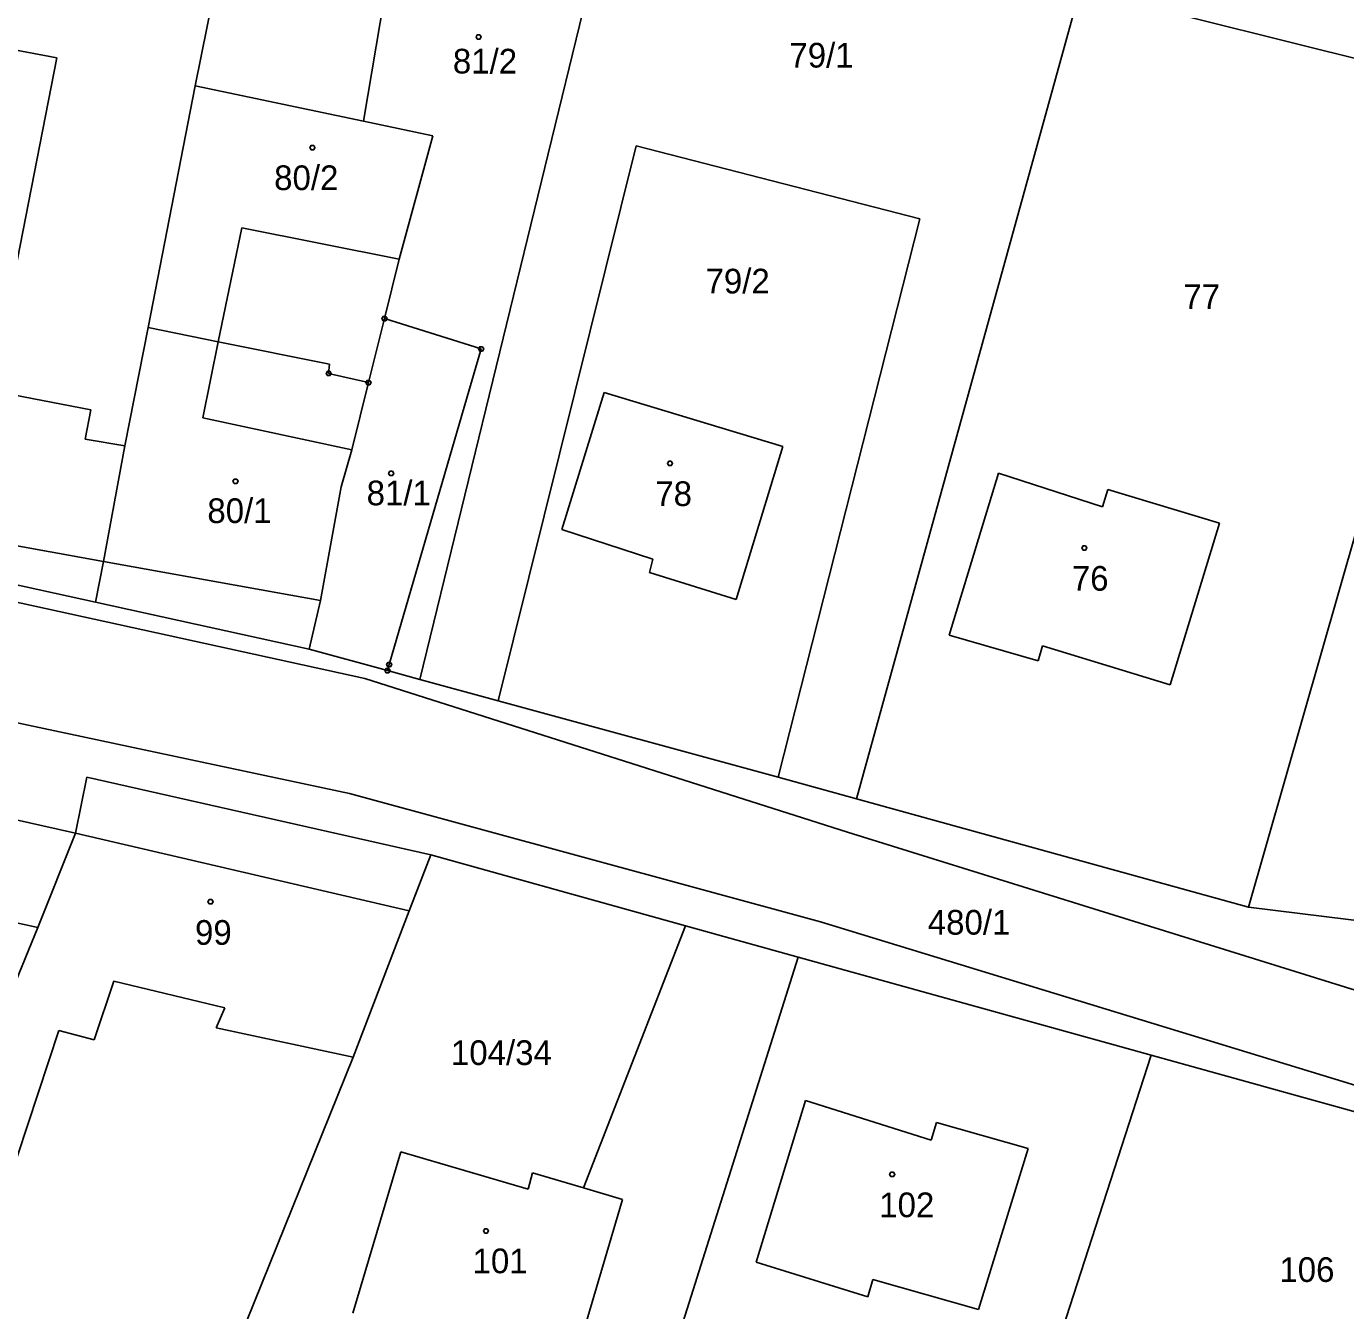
# Model space of a CAD drawing. Extents: x -634640 to -629202, y -1196156 to -1190068.
# Drawn here: x -631368.4 to -631277.6, y -1192711.2 to -1192622.8 of the extents above; entities that cross this region are included whole.
import ezdxf

# ---------------------------------------------------------------- set-up
doc = ezdxf.new("R2010")
doc.units = 0
for name, color, linetype in [('Vrstva 1', 7, 'Continuous'), ('Vrstva 2', 7, 'Continuous'), ('Vrstva 3', 7, 'Continuous'), ('Vrstva 4', 7, 'Continuous'), ('Vrstva 5', 7, 'Continuous'), ('Vrstva 8', 7, 'Continuous')]:
    doc.layers.add(name, color=color, linetype=linetype)

msp = doc.modelspace()

# ---------------------------------------------------------------- linework, layer by layer
at = {"layer": 'Vrstva 1'}
for p, q in [((-631342.04, -1192610.57), (-631345.22, -1192629.29)), ((-631341.34, -1192667.74), (-631327.93, -1192612.83)), ((-631356.81, -1192626.85), (-631354.23, -1192614.01)), ((-631311.26, -1192675.96), (-631295.87, -1192620.24)), ((-631295.87, -1192620.24), (-631268.16, -1192627.17)), ((-631360.06, -1192643.5), (-631356.81, -1192626.85)), ((-631284.27, -1192683.42), (-631268.16, -1192627.17)), ((-631345.22, -1192629.29), (-631340.44, -1192630.3)), ((-631340.44, -1192630.3), (-631342.77, -1192638.79)), ((-631335.95, -1192669.21), (-631326.44, -1192631)), ((-631326.44, -1192631), (-631306.91, -1192636.03)), ((-631306.91, -1192636.03), (-631316.66, -1192674.48)), ((-631342.77, -1192638.79), (-631343.78, -1192642.89)), ((-631343.78, -1192642.89), (-631344.88, -1192647.3)), ((-631337.12, -1192644.98), (-631343.78, -1192642.89)), ((-631361.66, -1192651.66), (-631360.06, -1192643.5)), ((-631360.06, -1192643.5), (-631355.22, -1192644.48)), ((-631355.22, -1192644.48), (-631347.55, -1192646.04)), ((-631343.45, -1192666.72), (-631337.12, -1192644.98)), ((-631347.55, -1192646.04), (-631347.62, -1192646.67)), ((-631347.62, -1192646.67), (-631344.88, -1192647.3)), ((-631344.88, -1192647.3), (-631346.02, -1192651.93)), ((-631331.57, -1192657.42), (-631328.65, -1192647.99)), ((-631328.65, -1192647.99), (-631316.34, -1192651.69)), ((-631363.12, -1192659.62), (-631361.66, -1192651.66)), ((-631346.02, -1192651.93), (-631346.75, -1192654.47)), ((-631316.34, -1192651.69), (-631319.55, -1192662.23)), ((-631304.89, -1192664.69), (-631301.49, -1192653.54)), ((-631301.49, -1192653.54), (-631294.33, -1192655.86)), ((-631346.75, -1192654.47), (-631348.17, -1192662.31)), ((-631294.33, -1192655.86), (-631293.95, -1192654.67)), ((-631293.95, -1192654.67), (-631286.25, -1192656.99)), ((-631325.28, -1192659.46), (-631331.57, -1192657.42)), ((-631286.25, -1192656.99), (-631289.67, -1192668.11)), ((-631345.12, -1192667.68), (-631387.55, -1192658.39)), ((-631363.68, -1192662.42), (-631378.54, -1192659.16)), ((-631363.68, -1192662.42), (-631363.12, -1192659.62)), ((-631325.52, -1192660.37), (-631325.28, -1192659.46)), ((-631319.55, -1192662.23), (-631325.52, -1192660.37)), ((-631348.97, -1192665.66), (-631363.68, -1192662.42)), ((-631348.17, -1192662.31), (-631348.97, -1192665.66)), ((-631298.76, -1192666.47), (-631304.89, -1192664.69)), ((-631343.57, -1192667.13), (-631348.97, -1192665.66)), ((-631298.45, -1192665.44), (-631298.76, -1192666.47)), ((-631289.67, -1192668.11), (-631298.45, -1192665.44)), ((-631384.86, -1192667.38), (-631346.18, -1192675.61)), ((-631343.57, -1192667.13), (-631343.45, -1192666.72)), ((-631341.34, -1192667.74), (-631343.57, -1192667.13)), ((-631311.89, -1192678.27), (-631345.12, -1192667.68)), ((-631335.95, -1192669.21), (-631341.34, -1192667.74)), ((-631316.66, -1192674.48), (-631335.95, -1192669.21)), ((-631365.05, -1192678.33), (-631383.23, -1192674.24)), ((-631364.28, -1192674.48), (-631365.05, -1192678.33)), ((-631340.58, -1192679.83), (-631364.28, -1192674.48)), ((-631311.26, -1192675.96), (-631316.66, -1192674.48)), ((-631346.18, -1192675.61), (-631313.75, -1192684.44)), ((-631284.27, -1192683.42), (-631311.26, -1192675.96)), ((-631365.05, -1192678.33), (-631367.66, -1192684.83)), ((-631259.47, -1192694.58), (-631311.89, -1192678.27)), ((-631340.58, -1192679.83), (-631342.08, -1192683.67)), ((-631323.05, -1192684.71), (-631340.58, -1192679.83)), ((-631342.08, -1192683.67), (-631345.92, -1192693.76)), ((-631274.56, -1192684.62), (-631284.27, -1192683.42)), ((-631367.66, -1192684.83), (-631376.35, -1192706.11)), ((-631330.07, -1192702.77), (-631323.05, -1192684.71)), ((-631315.29, -1192686.87), (-631323.05, -1192684.71)), ((-631313.75, -1192684.44), (-631261.8, -1192700.32)), ((-631315.29, -1192686.87), (-631326.27, -1192721.7)), ((-631290.96, -1192693.63), (-631315.29, -1192686.87)), ((-631345.92, -1192693.76), (-631356.56, -1192720.09)), ((-631290.96, -1192693.63), (-631302.52, -1192729.24)), ((-631262.31, -1192701.6), (-631290.96, -1192693.63)), ((-631318.17, -1192707.87), (-631314.77, -1192696.75)), ((-631314.77, -1192696.75), (-631306.11, -1192699.47)), ((-631306.11, -1192699.47), (-631305.75, -1192698.26)), ((-631305.75, -1192698.26), (-631299.44, -1192700.04)), ((-631299.44, -1192700.04), (-631302.87, -1192711.14)), ((-631345.96, -1192711.38), (-631342.65, -1192700.29)), ((-631342.65, -1192700.29), (-631333.88, -1192702.86)), ((-631333.88, -1192702.86), (-631333.57, -1192701.72)), ((-631333.57, -1192701.72), (-631330.07, -1192702.77)), ((-631330.07, -1192702.77), (-631327.38, -1192703.57)), ((-631327.38, -1192703.57), (-631330.63, -1192714.56)), ((-631310.48, -1192710.27), (-631318.17, -1192707.87)), ((-631310.14, -1192709.07), (-631310.48, -1192710.27)), ((-631302.87, -1192711.14), (-631310.14, -1192709.07))]:
    msp.add_line(p, q, dxfattribs=at)
at = {"layer": 'Vrstva 3'}
for points in [[(-631337.2, -1192623.34), (-631337.11, -1192623.49), (-631337.2, -1192623.64), (-631337.38, -1192623.64), (-631337.47, -1192623.49), (-631337.38, -1192623.34), (-631337.2, -1192623.34)], [(-631343.22, -1192653.4), (-631343.13, -1192653.55), (-631343.22, -1192653.7), (-631343.4, -1192653.7), (-631343.49, -1192653.55), (-631343.4, -1192653.4), (-631343.22, -1192653.4)]]:
    msp.add_lwpolyline(points, dxfattribs=at)
at = {"layer": 'Vrstva 4'}
for p, q in [((-631366.33, -1192624.94), (-631371.82, -1192623.91)), ((-631366.33, -1192624.94), (-631370.44, -1192645.84)), ((-631356.81, -1192626.85), (-631345.22, -1192629.29)), ((-631353.61, -1192636.65), (-631355.22, -1192644.48)), ((-631342.77, -1192638.79), (-631353.61, -1192636.65)), ((-631355.22, -1192644.48), (-631356.29, -1192649.73)), ((-631369.34, -1192648.15), (-631364, -1192649.18)), ((-631364, -1192649.18), (-631364.39, -1192651.2)), ((-631356.29, -1192649.73), (-631346.02, -1192651.93)), ((-631364.39, -1192651.2), (-631361.66, -1192651.66)), ((-631363.12, -1192659.62), (-631378.09, -1192656.92)), ((-631348.17, -1192662.31), (-631363.12, -1192659.62)), ((-631365.05, -1192678.33), (-631342.08, -1192683.67)), ((-631372.37, -1192683.81), (-631367.66, -1192684.83)), ((-631362.42, -1192688.53), (-631363.76, -1192692.57)), ((-631354.77, -1192690.36), (-631362.42, -1192688.53)), ((-631355.37, -1192691.73), (-631354.77, -1192690.36)), ((-631366.21, -1192691.93), (-631371.1, -1192706.74)), ((-631363.76, -1192692.57), (-631366.21, -1192691.93)), ((-631345.92, -1192693.76), (-631355.37, -1192691.73))]:
    msp.add_line(p, q, dxfattribs=at)
at = {"layer": 'Vrstva 5'}
for points in [[(-631348.65, -1192630.96), (-631348.56, -1192631.11), (-631348.65, -1192631.26), (-631348.83, -1192631.26), (-631348.92, -1192631.11), (-631348.83, -1192630.96), (-631348.65, -1192630.96)], [(-631324.02, -1192652.72), (-631323.93, -1192652.87), (-631324.02, -1192653.02), (-631324.2, -1192653.02), (-631324.29, -1192652.87), (-631324.2, -1192652.72), (-631324.02, -1192652.72)], [(-631353.94, -1192653.94), (-631353.85, -1192654.09), (-631353.94, -1192654.24), (-631354.12, -1192654.24), (-631354.21, -1192654.09), (-631354.12, -1192653.94), (-631353.94, -1192653.94)], [(-631295.48, -1192658.53), (-631295.39, -1192658.68), (-631295.48, -1192658.83), (-631295.66, -1192658.83), (-631295.75, -1192658.68), (-631295.66, -1192658.53), (-631295.48, -1192658.53)], [(-631355.66, -1192682.9), (-631355.57, -1192683.05), (-631355.66, -1192683.2), (-631355.84, -1192683.2), (-631355.93, -1192683.05), (-631355.84, -1192682.9), (-631355.66, -1192682.9)], [(-631308.71, -1192701.68), (-631308.62, -1192701.83), (-631308.71, -1192701.98), (-631308.89, -1192701.98), (-631308.98, -1192701.83), (-631308.89, -1192701.68), (-631308.71, -1192701.68)], [(-631336.69, -1192705.58), (-631336.6, -1192705.73), (-631336.69, -1192705.88), (-631336.87, -1192705.88), (-631336.96, -1192705.73), (-631336.87, -1192705.58), (-631336.69, -1192705.58)]]:
    msp.add_lwpolyline(points, dxfattribs=at)
at = {"layer": 'Vrstva 8'}
for points in [[(-631343.69, -1192642.74), (-631343.6, -1192642.89), (-631343.69, -1192643.04), (-631343.87, -1192643.04), (-631343.96, -1192642.89), (-631343.87, -1192642.74), (-631343.69, -1192642.74)], [(-631337.03, -1192644.83), (-631336.94, -1192644.98), (-631337.03, -1192645.13), (-631337.21, -1192645.13), (-631337.3, -1192644.98), (-631337.21, -1192644.83), (-631337.03, -1192644.83)], [(-631347.53, -1192646.52), (-631347.44, -1192646.67), (-631347.53, -1192646.82), (-631347.71, -1192646.82), (-631347.8, -1192646.67), (-631347.71, -1192646.52), (-631347.53, -1192646.52)], [(-631344.79, -1192647.15), (-631344.7, -1192647.3), (-631344.79, -1192647.45), (-631344.97, -1192647.45), (-631345.06, -1192647.3), (-631344.97, -1192647.15), (-631344.79, -1192647.15)], [(-631343.36, -1192666.57), (-631343.27, -1192666.72), (-631343.36, -1192666.87), (-631343.54, -1192666.87), (-631343.63, -1192666.72), (-631343.54, -1192666.57), (-631343.36, -1192666.57)], [(-631343.48, -1192666.98), (-631343.39, -1192667.13), (-631343.48, -1192667.28), (-631343.66, -1192667.28), (-631343.75, -1192667.13), (-631343.66, -1192666.98), (-631343.48, -1192666.98)]]:
    msp.add_lwpolyline(points, dxfattribs=at)

# ---------------------------------------------------------------- texts
at = {"layer": 'Vrstva 2'}
for s, p in [('79/1', (-631315.883, -1192625.6)), ('81/2', (-631339.063, -1192626.01)), ('80/2', (-631351.373, -1192634.04)), ('79/2', (-631321.663, -1192641.16)), ('77', (-631288.753, -1192642.24)), ('81/1', (-631345.003, -1192655.75)), ('78', (-631325.123, -1192655.8)), ('80/1', (-631355.973, -1192656.97)), ('76', (-631296.433, -1192661.63)), ('480/1', (-631306.354, -1192685.32)), ('99', (-631356.823, -1192686.02)), ('104/34', (-631339.197, -1192694.3)), ('102', (-631309.697, -1192704.78)), ('101', (-631337.707, -1192708.64)), ('106', (-631282.137, -1192709.24))]:
    msp.add_text(s, height=1.7, dxfattribs=at).set_placement(p)

doc.saveas('drawing.dxf')
